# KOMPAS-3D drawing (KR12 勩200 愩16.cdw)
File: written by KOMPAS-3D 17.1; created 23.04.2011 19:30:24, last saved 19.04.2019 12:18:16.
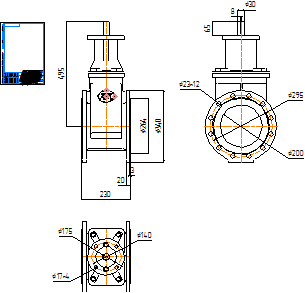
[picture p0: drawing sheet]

Sheet 1: A4, portrait

Title block, sheet 1: name: KR12 Ду200 Ру16; material: Внимание! Данный продукт является объектом авторского права ООО «Торговый Дом АДЛ». / Запрещается изменение, копирование, распространение / (в том числе путем копирования на другие сайты и ресурсы в Интернете) / или любое иное использование информации и объектов без предварительного / согласия правообладателя (ООО «Торговый Дом АДЛ»).; scale: 1:1; sheets: 1; organisation: ООО "Торговый дом АДЛ"; sheet format: A4; stored path: \\adlc.lan\data\АДЛ_ПКД\3D-модели\ADL production\Клиновые задвижки серии KR ГРАНАР\Клиновые задвижки KR12\KOMPAS 2D\KR12 Ду200 Ру16.cdw

Views: Спереди 4, Проекционный вид 5, Проекционный вид 6
Dimensions and other numbers on the sheet: 230; 20; 3; 495; 340; 264; 175; 17; 140; 65; 295; 200; 23; 30; 8; 1:1; 1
